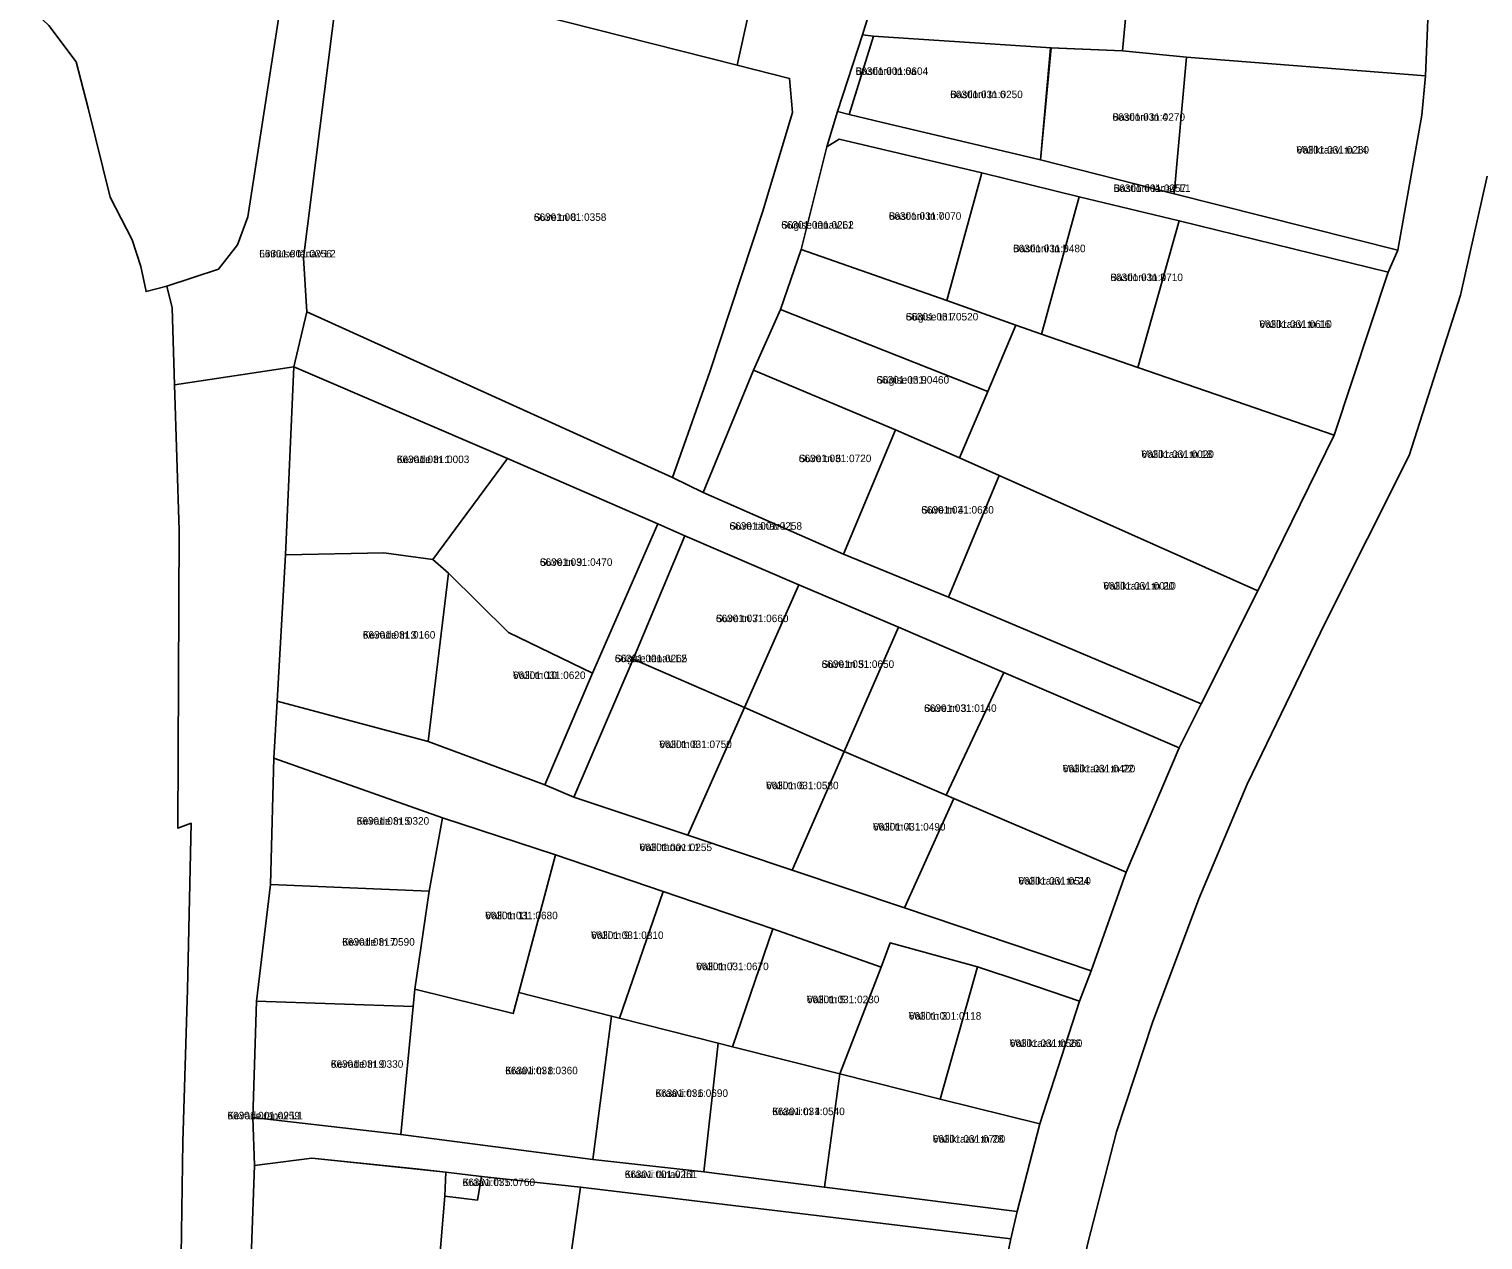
# Model space of a CAD drawing. Extents: x 632278 to 636344, y 6578401 to 6583362.
# Drawn here: x 633424.9 to 633715.5, y 6580851.5 to 6581093.5 of the extents above; entities that cross this region are included whole.
import ezdxf

# ---------------------------------------------------------------- set-up
doc = ezdxf.new("R2010")
doc.units = 0
for name, color, linetype in [('L_AADRESS', 7, 'Continuous'), ('PIIR', 7, 'Continuous'), ('TUNNUS', 7, 'Continuous')]:
    doc.layers.add(name, color=color, linetype=linetype)

msp = doc.modelspace()

# ---------------------------------------------------------------- linework, layer by layer
at = {"layer": 'PIIR'}
for points in [[(633615.05, 6580822.36), (633621.12, 6580851.71), (633622.34, 6580857.15), (633626.87, 6580874.69), (633634.82, 6580899.19), (633637.15, 6580905.29), (633644.15, 6580924.96), (633654.74, 6580949.86), (633659.12, 6580958.62), (633670.46, 6580981.21), (633685.73, 6581012.34), (633696.55, 6581044.87), (633698.45, 6581049.32), (633703.29, 6581076.27), (633704.01, 6581084.13), (633704.83, 6581105.14), (633703.93, 6581125.62), (633702.13, 6581129.97), (633695.62, 6581168.99), (633693.97, 6581174.56), (633683.34, 6581210.34), (633669.07, 6581245.32), (633665.29, 6581254.58), (633652.61, 6581285.65)], [(633429.59, 6581262.54), (633495.97, 6581227.32), (633486.35, 6581182.89), (633484.15, 6581164.83), (633479.55, 6581126.98), (633468.58, 6581055.98), (633466.5, 6581050.34), (633462.73, 6581045.47), (633452.38, 6581042.1), (633448.23, 6581041.03), (633447.22, 6581046.01), (633445.44, 6581051.35), (633441.07, 6581059.91), (633436.69, 6581077.69), (633434.26, 6581086.91), (633428.78, 6581094.18), (633422.55, 6581100.22)], [(633726.5, 6580758.41), (633714.62, 6580798.56), (633707.48, 6580822.49), (633680.59, 6580820.37), (633679.02, 6580795.42), (633675.25, 6580737.26), (633673.73, 6580676.19), (633624.35, 6580704.17), (633625.61, 6580767.44), (633627.36, 6580797.21), (633629.82, 6580819.98), (633636.47, 6580850.81), (633642.25, 6580873.05), (633649.43, 6580894.94), (633658.71, 6580919.64), (633668.34, 6580942.58), (633683.92, 6580974.81), (633700.7, 6581008.23), (633710.97, 6581040.33), (633716.32, 6581064.08)], [(633716.32, 6581064.08), (633710.97, 6581040.33), (633700.7, 6581008.23), (633683.92, 6580974.81), (633668.34, 6580942.58), (633658.71, 6580919.64), (633649.43, 6580894.94), (633642.25, 6580873.05), (633636.47, 6580850.81)], [(633455.15, 6580839.38), (633455.56, 6580871.09), (633456.49, 6580901.52), (633457.27, 6580934.74), (633454.57, 6580933.79), (633454.88, 6580993.31), (633453.95, 6581022.36), (633477.75, 6581025.98), (633476.13, 6580988.42), (633474.43, 6580959.18), (633473.79, 6580947.76), (633473.1, 6580922.48), (633470.33, 6580899.22), (633469.55, 6580875.97), (633469.9, 6580866.33), (633468.69, 6580833.28)]]:
    msp.add_lwpolyline(points, dxfattribs=at)
for points in [[(633479.55, 6581126.98), (633489.35, 6581124.69), (633487.08, 6581106.41), (633479.68, 6581047.76), (633480.39, 6581036.99), (633477.75, 6581025.98), (633453.95, 6581022.36), (633453.46, 6581037.79), (633452.38, 6581042.1), (633462.73, 6581045.47), (633466.5, 6581050.34), (633468.58, 6581055.98)], [(633570.9, 6581106.78), (633566.37, 6581086.29), (633487.08, 6581106.41), (633489.35, 6581124.69), (633491.52, 6581124.18), (633563.52, 6581108.4)], [(633591.48, 6581092.36), (633596.92, 6581110.03), (633642.1, 6581116.71), (633646.84, 6581117.35), (633647.5, 6581102.88), (633644.68, 6581102.79), (633643.43, 6581089.17), (633629.15, 6581089.76), (633600.67, 6581091.61), (633593.68, 6581092.04)], [(633570.9, 6581106.78), (633596.92, 6581110.03), (633591.48, 6581092.36), (633586.47, 6581076.99), (633584.3, 6581069.92), (633581.34, 6581057.94), (633579.2, 6581049.45), (633575.06, 6581037.47), (633569.68, 6581025.3), (633559.57, 6581000.86), (633553.49, 6581003.89), (633560.94, 6581024.97), (633571.45, 6581056.88), (633577.47, 6581076.82), (633576.86, 6581083.62), (633566.37, 6581086.29)], [(633553.49, 6581003.89), (633480.39, 6581036.99), (633479.68, 6581047.76), (633487.08, 6581106.41), (633566.37, 6581086.29), (633576.86, 6581083.62), (633577.47, 6581076.82), (633571.45, 6581056.88), (633560.94, 6581024.97)], [(633643.43, 6581089.17), (633644.68, 6581102.79), (633647.5, 6581102.88), (633704.83, 6581105.14), (633704.01, 6581084.13), (633656.24, 6581087.86)], [(633591.48, 6581092.36), (633593.68, 6581092.04), (633588.76, 6581076.44), (633586.47, 6581076.99)], [(633600.67, 6581091.61), (633629.15, 6581089.76), (633627.05, 6581067.32), (633595.46, 6581074.84), (633588.76, 6581076.44), (633593.68, 6581092.04)], [(633627.05, 6581067.32), (633629.06, 6581089.74), (633643.43, 6581089.17), (633656.24, 6581087.86), (633653.76, 6581060.58)], [(633653.76, 6581060.58), (633656.24, 6581087.86), (633704.01, 6581084.13), (633703.29, 6581076.27), (633698.45, 6581049.32)], [(633588.76, 6581076.44), (633595.46, 6581074.84), (633627.05, 6581067.32), (633653.76, 6581060.58), (633698.45, 6581049.32), (633696.55, 6581044.87), (633654.77, 6581055.19), (633634.74, 6581059.99), (633615.28, 6581064.78), (633586.78, 6581071.51), (633584.3, 6581069.92), (633586.47, 6581076.99)], [(633608.33, 6581039.23), (633579.2, 6581049.45), (633584.3, 6581069.92), (633586.78, 6581071.51), (633615.28, 6581064.78)], [(633608.33, 6581039.23), (633615.28, 6581064.78), (633634.74, 6581059.99), (633627.22, 6581032.54), (633622.13, 6581034.32)], [(633634.74, 6581059.99), (633654.77, 6581055.19), (633646.47, 6581025.84), (633627.22, 6581032.54)], [(633654.77, 6581055.19), (633696.55, 6581044.87), (633685.73, 6581012.34), (633646.47, 6581025.84)], [(633579.2, 6581049.45), (633608.33, 6581039.23), (633622.13, 6581034.32), (633616.48, 6581021.05), (633575.06, 6581037.47)], [(633480.39, 6581036.99), (633553.49, 6581003.89), (633559.57, 6581000.86), (633587.65, 6580988.56), (633608.63, 6580979.92), (633659.12, 6580958.62), (633654.74, 6580949.86), (633619.7, 6580964.89), (633598.67, 6580973.97), (633578.71, 6580982.43), (633555.93, 6580992.18), (633550.55, 6580994.62), (633520.5, 6581007.68), (633477.75, 6581025.98)], [(633575.06, 6581037.47), (633616.48, 6581021.05), (633610.85, 6581007.79), (633598.07, 6581013.37), (633569.68, 6581025.3)], [(633610.85, 6581007.79), (633616.48, 6581021.05), (633622.13, 6581034.32), (633627.22, 6581032.54), (633646.47, 6581025.84), (633685.73, 6581012.34), (633670.46, 6580981.21), (633618.74, 6581004.27)], [(633477.75, 6581025.98), (633520.5, 6581007.68), (633505.59, 6580987.5), (633495.74, 6580988.79), (633476.13, 6580988.42)], [(633569.68, 6581025.3), (633598.07, 6581013.37), (633587.65, 6580988.56), (633559.57, 6581000.86)], [(633598.07, 6581013.37), (633610.85, 6581007.79), (633618.74, 6581004.27), (633608.63, 6580979.92), (633587.65, 6580988.56)], [(633508.69, 6580984.74), (633505.59, 6580987.5), (633520.5, 6581007.68), (633550.55, 6580994.62), (633537.49, 6580964.72), (633520.69, 6580972.85)], [(633659.12, 6580958.62), (633608.63, 6580979.92), (633618.74, 6581004.27), (633670.46, 6580981.21)], [(633550.55, 6580994.62), (633555.93, 6580992.18), (633545.59, 6580967.56), (633533.77, 6580939.98), (633527.93, 6580942.45), (633537.49, 6580964.72)], [(633555.93, 6580992.18), (633578.71, 6580982.43), (633567.88, 6580957.91), (633545.59, 6580967.56)], [(633474.43, 6580959.18), (633476.13, 6580988.42), (633495.74, 6580988.79), (633505.59, 6580987.5), (633508.69, 6580984.74), (633504.66, 6580951.1)], [(633504.66, 6580951.1), (633508.69, 6580984.74), (633520.69, 6580972.85), (633537.49, 6580964.72), (633527.93, 6580942.45)], [(633578.71, 6580982.43), (633598.67, 6580973.97), (633587.81, 6580949.12), (633567.88, 6580957.91)], [(633608.18, 6580940.35), (633587.81, 6580949.12), (633598.67, 6580973.97), (633619.7, 6580964.89)], [(633545.59, 6580967.56), (633567.88, 6580957.91), (633556.53, 6580932.36), (633533.77, 6580939.98)], [(633608.18, 6580940.35), (633619.7, 6580964.89), (633654.74, 6580949.86), (633644.15, 6580924.96), (633609.69, 6580939.7)], [(633474.43, 6580959.18), (633504.66, 6580951.1), (633527.93, 6580942.45), (633533.77, 6580939.98), (633556.53, 6580932.36), (633577.39, 6580925.36), (633599.86, 6580917.83), (633637.15, 6580905.29), (633634.82, 6580899.19), (633623.49, 6580903.04), (633614.47, 6580906.08), (633596.97, 6580910.84), (633595.16, 6580906), (633573.54, 6580913.64), (633551.58, 6580921.11), (633530.09, 6580928.42), (633507.48, 6580935.82), (633473.79, 6580947.76)], [(633567.88, 6580957.91), (633587.81, 6580949.12), (633577.39, 6580925.36), (633556.53, 6580932.36)], [(633587.81, 6580949.12), (633608.18, 6580940.35), (633609.69, 6580939.7), (633599.86, 6580917.83), (633577.39, 6580925.36)], [(633507.48, 6580935.82), (633504.86, 6580921.18), (633473.1, 6580922.48), (633473.79, 6580947.76)], [(633609.69, 6580939.7), (633644.15, 6580924.96), (633637.15, 6580905.29), (633599.86, 6580917.83)], [(633504.86, 6580921.18), (633507.48, 6580935.82), (633530.09, 6580928.42), (633522.77, 6580900.93), (633521.63, 6580896.72), (633501.97, 6580901.61)], [(633530.09, 6580928.42), (633551.58, 6580921.11), (633542.87, 6580895.79), (633541.28, 6580896.2), (633522.77, 6580900.93)], [(633473.1, 6580922.48), (633504.86, 6580921.18), (633501.97, 6580901.61), (633501.62, 6580898.11), (633470.33, 6580899.22)], [(633551.58, 6580921.11), (633573.54, 6580913.64), (633565.46, 6580890.08), (633562.61, 6580890.81), (633542.87, 6580895.79)], [(633595.17, 6580905.99), (633586.93, 6580884.67), (633565.46, 6580890.08), (633573.54, 6580913.64)], [(633595.17, 6580905.99), (633596.97, 6580910.84), (633614.47, 6580906.08), (633606.95, 6580879.6), (633586.93, 6580884.67)], [(633623.5, 6580903.04), (633634.82, 6580899.19), (633626.87, 6580874.69), (633606.95, 6580879.6), (633614.47, 6580906.08)], [(633501.62, 6580898.11), (633501.97, 6580901.61), (633521.63, 6580896.72), (633522.77, 6580900.93), (633541.28, 6580896.2), (633537.53, 6580867.57), (633499.16, 6580872.54)], [(633501.62, 6580898.11), (633499.16, 6580872.54), (633469.55, 6580875.97), (633470.33, 6580899.22)], [(633541.28, 6580896.2), (633542.87, 6580895.79), (633562.61, 6580890.81), (633559.74, 6580865.06), (633537.53, 6580867.57)], [(633562.61, 6580890.81), (633565.46, 6580890.08), (633586.93, 6580884.67), (633583.85, 6580862.01), (633559.74, 6580865.06)], [(633586.93, 6580884.67), (633606.95, 6580879.6), (633626.87, 6580874.69), (633622.34, 6580857.15), (633583.85, 6580862.01)], [(633469.55, 6580875.97), (633499.16, 6580872.54), (633537.53, 6580867.57), (633559.74, 6580865.06), (633583.85, 6580862.01), (633622.34, 6580857.15), (633621.12, 6580851.71), (633535.09, 6580862.05), (633515.3, 6580864.18), (633508.14, 6580865.03), (633481.36, 6580867.82), (633469.9, 6580866.33)], [(633469.9, 6580866.33), (633481.36, 6580867.82), (633502.23, 6580865.66), (633508.14, 6580865.03), (633507.95, 6580860.22), (633505.54, 6580831.5), (633499.56, 6580831.92), (633468.69, 6580833.28)], [(633508.14, 6580865.03), (633515.3, 6580864.18), (633514.49, 6580859.45), (633507.95, 6580860.22)], [(633507.95, 6580860.22), (633514.49, 6580859.45), (633515.3, 6580864.18), (633535.09, 6580862.05), (633530.54, 6580829.88), (633527.79, 6580829.9), (633505.54, 6580831.5)], [(633615.05, 6580822.36), (633549.79, 6580828.24), (633530.54, 6580829.88), (633535.09, 6580862.05), (633621.12, 6580851.71)]]:
    msp.add_lwpolyline(points, close=True, dxfattribs=at)

# ---------------------------------------------------------------- texts
at = {"layer": 'L_AADRESS'}
for s, p in [('Bastioni tn 6a', (633590.07, 6581084.33)), ('Bastioni tn 6', (633608.99, 6581079.68)), ('Bastioni tn 4', (633641.42, 6581075.16)), ('Vallikraavi tn 14', (633678.2, 6581068.59)), ('Bastioni tänav L1', (633641.65, 6581060.93)), ('Suve tn 8', (633525.75, 6581055.15)), ('Bastioni tn 7', (633596.7, 6581055.37)), ('Sügise tänav L1', (633575.21, 6581053.6)), ('Linnuse tänav L2', (633470.87, 6581047.85)), ('Bastioni tn 5', (633621.54, 6581048.89)), ('Bastioni tn 3', (633641, 6581043.12)), ('Sügise tn 7', (633600.09, 6581035.25)), ('Vallikraavi tn 16', (633670.78, 6581033.77)), ('Sügise tn 9', (633594.26, 6581022.63)), ('Kevade tn 1', (633498.36, 6581006.74)), ('Suve tn 6', (633578.72, 6581006.93)), ('Vallikraavi tn 18', (633647.2, 6581007.77)), ('Suve tn 4', (633603.2, 6580996.65)), ('Suve tänav L1', (633564.86, 6580993.42)), ('Suve tn 9', (633526.96, 6580986.2)), ('Vallikraavi tn 20', (633639.6, 6580981.45)), ('Suve tn 7', (633562.15, 6580974.95)), ('Kevade tn 3', (633491.56, 6580971.66)), ('Sügise tänav L2', (633541.93, 6580966.95)), ('Suve tn 5', (633583.28, 6580965.81)), ('Valli tn 10', (633521.58, 6580963.59)), ('Suve tn 3', (633603.76, 6580957.01)), ('Valli tn 8', (633550.83, 6580949.78)), ('Vallikraavi tn 22', (633631.48, 6580944.93)), ('Valli tn 6', (633572.17, 6580941.56)), ('Kevade tn 5', (633490.33, 6580934.47)), ('Valli tn 4', (633593.54, 6580933.3)), ('Valli tänav L1', (633546.87, 6580929.19)), ('Vallikraavi tn 24', (633622.61, 6580922.49)), ('Valli tn 11', (633516.03, 6580915.57)), ('Kevade tn 7', (633487.45, 6580910.29)), ('Valli tn 9', (633537.18, 6580911.63)), ('Valli tn 7', (633558.2, 6580905.39)), ('Valli tn 5', (633580.32, 6580898.79)), ('Valli tn 3', (633600.7, 6580895.5)), ('Vallikraavi tn 26', (633620.89, 6580890.04)), ('Kevade tn 9', (633485.16, 6580885.88)), ('Kraavi tn 8', (633520.04, 6580884.59)), ('Kraavi tn 6', (633550.07, 6580880.06)), ('Kevade tänav L1', (633464.5, 6580875.58)), ('Kraavi tn 4', (633573.41, 6580876.41)), ('Vallikraavi tn 28', (633605.48, 6580870.91)), ('Kraavi tänav L1', (633543.92, 6580863.84)), ('Kraavi tn 5', (633511.5, 6580862.24))]:
    msp.add_text(s, height=1.5, dxfattribs=at).set_placement(p)
at = {"layer": 'TUNNUS'}
for s, p in [('66301:001:0604', (633590.07, 6581084.33)), ('66301:031:0250', (633608.99, 6581079.68)), ('66301:031:0270', (633641.42, 6581075.16)), ('66301:031:0280', (633678.2, 6581068.59)), ('66301:001:0257', (633641.65, 6581060.93)), ('66301:001:0358', (633525.75, 6581055.15)), ('66301:031:0070', (633596.7, 6581055.37)), ('66301:001:0262', (633575.21, 6581053.6)), ('66301:001:0256', (633470.87, 6581047.85)), ('66301:031:0480', (633621.54, 6581048.89)), ('66301:031:0710', (633641, 6581043.12)), ('66301:031:0520', (633600.09, 6581035.25)), ('66301:031:0610', (633670.78, 6581033.77)), ('66301:031:0460', (633594.26, 6581022.63)), ('66301:031:0003', (633498.36, 6581006.74)), ('66301:031:0720', (633578.72, 6581006.93)), ('66301:031:0020', (633647.2, 6581007.77)), ('66301:031:0630', (633603.2, 6580996.65)), ('66301:001:0258', (633564.86, 6580993.42)), ('66301:031:0470', (633526.96, 6580986.2)), ('66301:031:0010', (633639.6, 6580981.45)), ('66301:031:0660', (633562.15, 6580974.95)), ('66301:031:0160', (633491.56, 6580971.66)), ('66301:001:0265', (633541.93, 6580966.95)), ('66301:031:0650', (633583.28, 6580965.81)), ('66301:031:0620', (633521.58, 6580963.59)), ('66301:031:0140', (633603.76, 6580957.01)), ('66301:031:0750', (633550.83, 6580949.78)), ('66301:031:0420', (633631.48, 6580944.93)), ('66301:031:0580', (633572.17, 6580941.56)), ('66301:031:0320', (633490.33, 6580934.47)), ('66301:031:0490', (633593.54, 6580933.3)), ('66301:001:0255', (633546.87, 6580929.19)), ('66301:031:0510', (633622.61, 6580922.49)), ('66301:031:0680', (633516.03, 6580915.57)), ('66301:031:0590', (633487.45, 6580910.29)), ('66301:031:0310', (633537.18, 6580911.63)), ('66301:031:0670', (633558.2, 6580905.39)), ('66301:031:0230', (633580.32, 6580898.79)), ('66301:001:0118', (633600.7, 6580895.5)), ('66301:031:0560', (633620.89, 6580890.04)), ('66301:031:0330', (633485.16, 6580885.88)), ('66301:031:0360', (633520.04, 6580884.59)), ('66301:031:0690', (633550.07, 6580880.06)), ('66301:001:0259', (633464.5, 6580875.58)), ('66301:031:0540', (633573.41, 6580876.41)), ('66301:031:0700', (633605.48, 6580870.91)), ('66301:001:0261', (633543.92, 6580863.84)), ('66301:031:0760', (633511.5, 6580862.24))]:
    msp.add_text(s, height=1.5, dxfattribs=at).set_placement(p)

doc.saveas('drawing.dxf')
